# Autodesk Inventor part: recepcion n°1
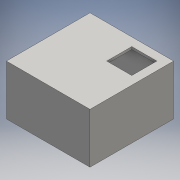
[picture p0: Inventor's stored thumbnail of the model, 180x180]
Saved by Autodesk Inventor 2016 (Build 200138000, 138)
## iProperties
Created: 2016-06
Part Number: recepcion n°1
Material: Genérico
Document SubType Name: Modeling
Designer: adm
Density: 1 g/cm^3
Appearance: Valor por defecto
Author: adm
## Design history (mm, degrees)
sketch "Boceto1"
  geometry: L1 (-50, -50)-(50, -50); L2 (50, -50)-(50, 50); L3 (50, 50)-(-50, 50); L4 (-50, 50)-(-50, -50); L5 (-50, -50)-(50, 50); L6 (50, -50)-(-50, 50); 1 further point
  constraints: 12 end point, 2 midpoint, 2 parallel, 1 horizontal, 1 perpendicular
  dimensions: "d0" = 100 distance of L3.end L2.end; "d1" = 100 distance of L2.end L1.end
extrude "Extrusión1" new body sketch "Boceto1" distance "d2" = 60; taper "d3" = 0 deg
feature "Vaciado1" dims "d4" = 3
sketch "Boceto2"
  geometry: L1 (-50, 50)-(-50, -50) reference; L2 (50, -50)-(-50, -50); L3 (-50, -50)-(-50, 50); L4 (-50, 50)-(50, 50); L5 (50, 50)-(50, -50); L6 (10, 10)-(40, 10); L7 (40, 10)-(40, 40); L8 (40, 40)-(10, 40); L9 (10, 40)-(10, 10); L10 (10, 10)-(40, 40); L11 (40, 10)-(10, 40); 2 further points
  constraints: 20 end point, 4 parallel, 2 horizontal, 2 midpoint, 2 perpendicular
  dimensions: "d5" = 30 distance of L8.end L7.end; "d6" = 30 distance of L7.end L6.end; "d7" = 25 distance from line of point (25, 25) L4; "d8" = 25 distance from line of L5 point (25, 25); "d9" = 100 distance between parallel lines of L5 L1; "d10" = 100 distance between parallel lines of L2 L4
extrude "Extrusión2" join sketch "Boceto2" distance "d11" = 3; taper "d12" = 0 deg
sketch "Boceto3"
  geometry: L1 (0, 100)-(0, 0) reference; L2 (0, 100)-(60, 100) reference; L3 (20, 90)-(10, 90); L4 (10, 90)-(10, 80); L5 (10, 80)-(20, 80); L6 (20, 80)-(20, 90); L7 (20, 90)-(10, 80); L8 (10, 90)-(20, 80); 2 further points
  constraints: 12 end point, 2 midpoint, 2 parallel, 1 horizontal, 1 perpendicular
  dimensions: "d13" = 15 distance from line of point (15, 85) L1; "d14" = 15 distance from line of point (15, 85) L2; "d15" = 10 distance of L5.end L4.end; "d16" = 10 distance of L4.end L3.end
extrude "Extrusión3" cut sketch "Boceto3" distance "d17" = 10; taper "d18" = 0 deg
node "Sólido1"
